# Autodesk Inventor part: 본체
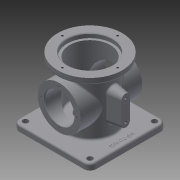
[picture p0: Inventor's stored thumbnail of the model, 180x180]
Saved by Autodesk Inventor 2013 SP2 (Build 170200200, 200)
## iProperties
Created: 2017-08
Part Number: 본체
Material: 알루미늄 6061
Document SubType Name: Modeling
Designer: mduedu
Density: 2.71 g/cm^3
Mass: 872.327 g
Surface Area: 642.238 cm^2
Volume: 321.892 cm^3
Author: mduedu
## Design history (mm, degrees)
sketch "스케치1"
  geometry: L1 (-62.5, -62.5)-(62.5, -62.5); L2 (62.5, -62.5)-(62.5, 62.5); L3 (62.5, 62.5)-(-62.5, 62.5); L4 (-62.5, 62.5)-(-62.5, -62.5); L5 (-62.5, -62.5)-(62.5, 62.5); L6 (62.5, -62.5)-(-62.5, 62.5); 1 further point
  constraints: 12 end point, 2 midpoint, 2 parallel, 1 horizontal, 1 perpendicular
  dimensions: "d232" = 125 distance of L3.end L2.end; "d233" = 125 distance of L2.end L1.end
extrude "돌출1" new body sketch "스케치1" distance "d5" = 10; taper "d6" = 0 deg
sketch "스케치2"
  geometry: C1 r 38 at (0, 0); 1 further point
  constraints: 1 centre point, 1 coincident
  dimensions: "d111" = 76 diameter of C1
extrude "돌출2" join sketch "스케치2" distance "d12" = 88; taper "d13" = 0 deg
sketch "스케치3"
  geometry: C1 r 52.5 at (0, 0); 1 further point
  constraints: 1 centre point, 1 coincident
  dimensions: "d114" = 105 diameter of C1
extrude "돌출3" join sketch "스케치3" distance "d19" = 10; taper "d20" = 0 deg
sketch "스케치4"
  geometry: C1 r 33 at (0, 0); 1 further point
  constraints: 1 centre point, 1 coincident
  dimensions: "d115" = 66 diameter of C1
extrude "돌출4" cut sketch "스케치4" distance "d26" = 86; taper "d27" = 0 deg
sketch "스케치5"
  geometry: C1 r 37 at (0, 0); 1 further point
  constraints: 1 centre point, 1 coincident
  dimensions: "d116" = 74 diameter of C1
extrude "돌출5" cut sketch "스케치5" distance "d29" = 7; taper "d30" = 0 deg
node "작업 평면1"
sketch "스케치18"
  geometry: L1 (-62.5, 0)-(62.5, 0) reference; C1 r 35 at (0, 54); 1 further point
  constraints: 1 centre point, 1 vertical alignment
  dimensions: "d118" = 70 diameter of C1; "d234" = 54 distance from line of C1.centre L1
extrude "돌출9" join sketch "스케치18" stored distance "d120" = 10; taper "d121" = 0 deg
hole "구멍8" diameter "d124" = 48; stored, may be unused: countersink angle "d128" = 90 deg, drill point angle "d130" = 118 deg; dims "d122" = 10, "d123" = 10, "d125" = 6, "d126" = 4, "d127" = 2, "d129" = 8
sketch "스케치9"
  geometry: C1 r 33 at (0, 0); 1 further point
  constraints: 1 centre point, 1 coincident
  dimensions: "d131" = 66 diameter of C1
extrude "돌출8" cut sketch "스케치9" distance "d43" = 16; taper "d44" = 0 deg
node "작업 평면2"
fillet "모깎기9" dims "d137" = 3
fillet "모깎기10" dims "d138" = 3
chamfer "모따기2" distance "d139" = 1; stored, may be unused: second distance "d140" = 2, angle "d141" = 45 deg
fillet "모깎기11" dims "d142" = 3
fillet "모깎기12" dims "d143" = 3
fillet "모깎기13" dims "d144" = 3
node "작업 평면3"
sketch "스케치20"
  geometry: L1 (108, -52.5)-(108, 52.5) reference; L2 (37, 7)-(71, 7); L3 (37, -7)-(71, -7); L4 (0, -33)-(0, 33) reference; A1 r 7 centre (37, 0) between (37, 7) and (37, -7); A2 r 7 centre (71, 0) between (71, 7) and (71, -7); 1 further point
  constraints: 4 end point, 4 point on circle, 3 tangent, 2 centre point, 2 horizontal alignment, 1 parallel, 1 perpendicular
  dimensions: "d203" = 14 diameter of A1; "d206" = 30 distance edge to line of A2 L1; "d207" = 48 dimension on A2 A1 (derived); "d236" = 30 distance edge to line of A1 L4
extrude "돌출10" join sketch "스케치20" stored distance "d152" = 10; taper "d153" = 10 deg
sketch "스케치21"
  geometry: C1 r 7 at (0, 71) reference; C2 r 7 at (0, 37) reference; 3 further points
  constraints: 2 coincident
hole "구멍12" sketch "스케치21" at (0, 71), (0, 37) diameter "d219" = 4.134; stored, may be unused: countersink angle "d223" = 90 deg, drill point angle "d225" = 118 deg; dims "d220" = 6, "d221" = 4, "d222" = 2, "d224" = 8
fillet "모깎기18" dims "d229" = 3
sketch "스케치23"
  geometry: C1 r 20 at (0, 0); 1 further point
  constraints: 1 centre point, 1 coincident
  dimensions: "d168" = 40 diameter of C1
extrude "돌출12" cut sketch "스케치23" stored distance "d169" = 148.25; taper "d170" = 0 deg
sketch "스케치28"
  geometry: L1 (62.5, -62.5)-(62.5, 62.5) reference; 2 further points
  constraints: 1 horizontal alignment, 1 other
  dimensions: "d238" = 10 distance from line of point (52.5, 0) L1
feature "엠보싱4" sketch "스케치28" dims "d239" = 0.5, "d240" = 0
sketch "스케치25" dims "d178" = 58
  geometry: C1 r 35 at (0, 0) reference; 3 further points
  constraints: 2 vertical alignment, 1 coincident, 2 other
hole "구멍10" sketch "스케치25" at (0, 29) diameter "d179" = 3.242; stored, may be unused: countersink angle "d183" = 90 deg, drill point angle "d185" = 118 deg; dims "d180" = 4, "d181" = 4, "d182" = 2, "d184" = 6
sketch "스케치26" dims "d189" = 90
  geometry: 3 further points
  constraints: 2 vertical alignment, 1 coincident, 2 other
hole "구멍11" sketch "스케치26" at (0, 45) diameter "d190" = 3.242; stored, may be unused: countersink angle "d194" = 90 deg, drill point angle "d196" = 118 deg; dims "d191" = 4, "d192" = 4, "d193" = 2, "d195" = 6
chamfer "모따기4" distance "d200" = 1; stored, may be unused: second distance "d201" = 2, angle "d202" = 45 deg
fillet "모깎기19" dims "d241" = 10
sketch "스케치29"
  geometry: A1 r 10 centre (-52.5, 52.5) between (-52.5, 62.5) and (-62.5, 52.5) reference; A2 r 10 centre (52.5, 52.5) between (62.5, 52.5) and (52.5, 62.5) reference; A3 r 10 centre (52.5, -52.5) between (52.5, -62.5) and (62.5, -52.5) reference; A4 r 10 centre (-52.5, -52.5) between (-62.5, -52.5) and (-52.5, -62.5) reference; 5 further points
  constraints: 4 coincident
hole "구멍13" sketch "스케치29" at (-52.5, 52.5), (52.5, 52.5), (52.5, -52.5), (-52.5, -52.5) diameter "d242" = 9; stored, may be unused: countersink angle "d246" = 90 deg, drill point angle "d248" = 118 deg; dims "d243" = 6, "d244" = 4, "d245" = 2, "d247" = 8
fillet "모깎기20" dims "d249" = 3
node "솔리드1"
mirror "대칭2"
pattern_circular "원형 패턴1" dims angle "d187" = 360 deg
mirror "대칭3"
pattern_circular "원형 패턴2" dims angle "d198" = 360 deg
other parameters: "d147" = 58
